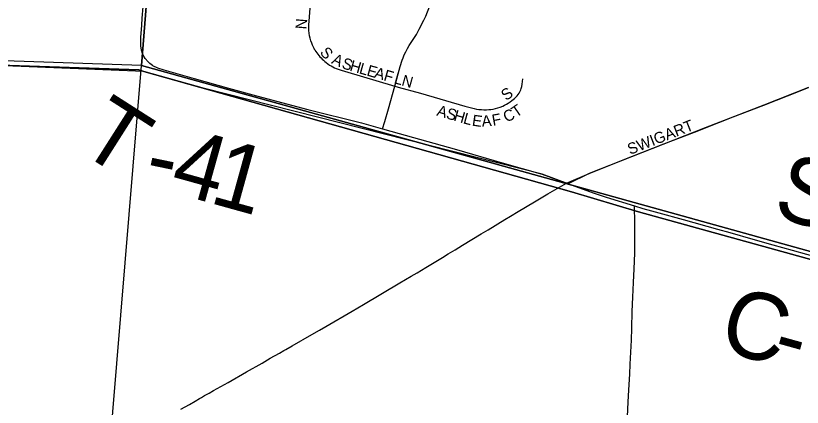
# Model space of a CAD drawing. Extents: x 1410790 to 1770854, y 448063 to 770588.
# Drawn here: x 1521556 to 1525089, y 615085 to 616842 of the extents above; entities that cross this region are included whole.
import ezdxf

# ---------------------------------------------------------------- set-up
doc = ezdxf.new("R2010")
doc.units = 0
for name, color, linetype in [('GM_X_City_Street', 7, 'Continuous'), ('GM_X_City_Street_Text', 7, 'Continuous'), ('GM_X_Corporation', 7, 'Continuous'), ('GM_X_County_Road', 7, 'Continuous'), ('GM_X_County_Road_Text', 7, 'Continuous'), ('GM_X_Section', 7, 'Continuous'), ('GM_X_Township', 7, 'Continuous'), ('GM_X_Township_Road', 7, 'Continuous'), ('GM_X_Township_Road_Text', 7, 'Continuous')]:
    doc.layers.add(name, color=color, linetype=linetype)

msp = doc.modelspace()

# ---------------------------------------------------------------- linework, layer by layer
at = {"layer": 'GM_X_City_Street'}
for points in [[(1522170.2, 616619.6), (1522158.5, 616627.2), (1522151.1, 616635), (1522137.6, 616650.4), (1522126.9, 616668.1), (1522120, 616687.5), (1522117.2, 616707.8), (1522117.6, 616744.5), (1522122.3, 616799.9), (1522123.6, 616831.2), (1522128.6, 616881.4), (1522135.7, 616983.1)], [(1523258.4, 616526.2), (1523283, 616614.2), (1523291.5, 616642.1), (1523295.9, 616654), (1523301.1, 616666.5), (1523307.8, 616680.5), (1523315.3, 616695), (1523323.1, 616709.2), (1523337.4, 616730.9), (1523355.4, 616758.6), (1523368.6, 616781.6), (1523389.4, 616822.8), (1523397.6, 616840.5), (1523405.7, 616859), (1523411.5, 616874.3), (1523417.1, 616890.1), (1523420.9, 616902.5), (1523424.2, 616915.8), (1523426.1, 616925.1), (1523427.7, 616935.7), (1523428.7, 616945.9), (1523428.9, 616955.5)], [(1522899.9, 616687.9), (1522896.1, 616694.8), (1522892.6, 616701.8), (1522888.7, 616710.2), (1522885.3, 616718.7), (1522882, 616729.1), (1522878.6, 616741.3), (1522875.9, 616752.6), (1522874.1, 616764.4), (1522872.9, 616775.6), (1522872.2, 616787.7), (1522872.6, 616802), (1522873.4, 616817.6), (1522878.2, 616876.8), (1522884.6, 616945.2)], [(1522899.9, 616687.9), (1522903.6, 616681.6), (1522907.7, 616675.5), (1522912.3, 616669.5), (1522917, 616663.8), (1522922.2, 616657.8), (1522927.2, 616652.7), (1522932.3, 616647.7), (1522938.3, 616642.1), (1522944.6, 616636.5), (1522950.7, 616631.7), (1522958.1, 616626.3), (1522965.7, 616621.1), (1522972.6, 616616.7), (1522980.2, 616612.6), (1522987.8, 616608.9), (1522995.5, 616605.8), (1523003.6, 616602.6), (1523017.3, 616598.1), (1523033, 616593.1), (1523258.4, 616526.2)], [(1523258.4, 616526.2), (1523273.4, 616522.1), (1523374.5, 616494), (1523573.5, 616436.8), (1523614.4, 616425.9), (1523626.1, 616423.6), (1523636.6, 616422), (1523647.6, 616421), (1523658.5, 616420.4), (1523670.2, 616420.4), (1523681.5, 616421), (1523689.9, 616421.8), (1523700.5, 616423.5), (1523711.2, 616425.7), (1523721.4, 616428.4), (1523732.5, 616432), (1523743.5, 616436.5), (1523751.8, 616440.3), (1523760.6, 616444.8), (1523768, 616449.4), (1523776.6, 616455.4), (1523784.1, 616461.1), (1523790.2, 616465.7), (1523796.9, 616471.3), (1523802.1, 616476.1), (1523808.1, 616482.4), (1523812.5, 616488.2), (1523817.1, 616495), (1523820.8, 616501.2), (1523824.1, 616509), (1523826.4, 616516), (1523828.6, 616524.7), (1523830.3, 616535.3), (1523833.4, 616558.4)], [(1523203.1, 616334.8), (1523213.1, 616368.1), (1523230, 616424.6), (1523258.4, 616526.2)], [(1524030, 616091.4), (1524131.4, 616134), (1524277.5, 616192.8), (1524467, 616267), (1524604.6, 616320), (1524714.4, 616363.5), (1524778.6, 616388.2), (1524916.1, 616440.7), (1525022.8, 616482.6), (1525116.2, 616520.4)]]:
    msp.add_lwpolyline(points, dxfattribs=at)
at = {"layer": 'GM_X_Corporation'}
msp.add_lwpolyline([(1525116.2, 616520.4), (1524916.1, 616440.7), (1524652.5, 616339), (1524131.4, 616134), (1524037.4, 616088.6), (1523920.1, 616131.6), (1522403.3, 616516.1), (1522130.9, 616592.7), (1521210.6, 616629.9)], dxfattribs=at)
at = {"layer": 'GM_X_County_Road'}
for points in [[(1522296.8, 615076.6), (1522335.9, 615098), (1522361.5, 615112.7), (1522381.1, 615124.4), (1522390.2, 615129.3), (1522403.8, 615137.5), (1522424.6, 615149.3), (1522443.8, 615160.7), (1522509.3, 615197.1), (1522591.6, 615243.6), (1522662.7, 615283.5), (1522699.1, 615305.4), (1522740.6, 615328.6), (1522760.6, 615339.9), (1522769.1, 615344.7), (1522797, 615361.7), (1522885.3, 615412.1), (1522919.5, 615431.6), (1522948.2, 615447.5), (1523067.7, 615516.1), (1523118, 615546.9), (1523281.8, 615643.7), (1523332.7, 615673.6), (1523358.4, 615688.1), (1523378.1, 615699.9), (1523397.7, 615711.8), (1523428.4, 615730.7), (1523473.2, 615757.9), (1523498, 615773.7), (1523529.1, 615792), (1523562.8, 615812.4), (1523604.8, 615837.9), (1523646.9, 615863.3), (1523677.8, 615881.9), (1523753.4, 615928.1), (1523778.5, 615943.4), (1523813.3, 615963.7), (1523885.5, 616006.8), (1523946.6, 616043.7), (1524030, 616091.4)], [(1524030, 616091.4), (1524088.4, 616069.3), (1524150.1, 616047), (1524207.7, 616028.5), (1524335.3, 615989.4)], [(1524335.3, 615989.4), (1524373.4, 615977.9), (1524411.2, 615967.2)], [(1524411.2, 615967.2), (1524445.2, 615957.5), (1524553.7, 615927.9), (1524707.6, 615885), (1524764.1, 615870), (1524866.1, 615840.2), (1524957.4, 615814.3), (1525044.2, 615790.1), (1525172.7, 615754.6)]]:
    msp.add_lwpolyline(points, dxfattribs=at)
at = {"layer": 'GM_X_Section'}
for points in [[(1522551.9, 622046.6), (1522119.9, 616619.5), (1516186.2, 616821.5), (1516639.8, 622176)], [(1527751.7, 620502.8), (1527349.3, 615167.2), (1522119.9, 616619.5), (1522551.9, 622046.6)], [(1522119.9, 616619.5), (1527349.3, 615167.2), (1526943.5, 609749.7), (1521677.3, 611270.6)]]:
    msp.add_lwpolyline(points, close=True, dxfattribs=at)
at = {"layer": 'GM_X_Township'}
for points in [[(1536959.1, 614403.3), (1531259.4, 614833.9), (1529991.4, 614929.8), (1529552.3, 614962.9), (1527330.8, 615130.8), (1527316.2, 615134.9), (1526855.2, 615264.5), (1525559.8, 615628.7), (1524353.6, 615961.7), (1524051.6, 616052.7), (1522130.9, 616592.7), (1522108.4, 616599.1), (1518670.6, 616715.2), (1518385.8, 616724.8), (1518142.2, 616733), (1517607.5, 616751.1), (1517456.2, 616756.2), (1517166.1, 616772.8), (1516773.1, 616795.4), (1516487.5, 616797.3), (1516179.6, 616799.3), (1516259.6, 617762.4), (1516373.4, 619132.2), (1516461.1, 620230.1)], [(1515651.7, 611077.8), (1515731.8, 611411.8), (1515919.3, 613667.1), (1515954.1, 614086), (1516097.7, 615813.6), (1516178.5, 616785.8), (1516179.6, 616799.3), (1516487.5, 616797.3), (1516773.1, 616795.4), (1517166.1, 616772.8), (1517456.2, 616756.2), (1517607.5, 616751.1), (1518142.2, 616733), (1518385.8, 616724.8), (1518670.6, 616715.2), (1522108.4, 616599.1), (1522130.9, 616592.7), (1524051.6, 616052.7), (1524353.6, 615961.7), (1525559.8, 615628.7)]]:
    msp.add_lwpolyline(points, dxfattribs=at)
at = {"layer": 'GM_X_Township_Road'}
for points in [[(1522170.2, 616619.6), (1522193.2, 616609.1), (1522221.3, 616599), (1522356.9, 616560.6), (1522511.3, 616516.7), (1522637.8, 616482.8), (1522868.2, 616422.1), (1523108.5, 616361.9), (1523203.1, 616334.8)], [(1523203.1, 616334.8), (1523240.9, 616323.9), (1523535.2, 616242), (1523740.2, 616182.7), (1523920.1, 616131.6), (1524030, 616091.4)], [(1524301.8, 615011.6), (1524307.4, 615108.3), (1524310.3, 615163.4), (1524313.6, 615233.9), (1524315.9, 615278.9), (1524321.1, 615386.8), (1524323.1, 615440.2), (1524324.7, 615514.4), (1524328.3, 615579.6), (1524331, 615645.2), (1524334.3, 615706.9), (1524337.2, 615776.1), (1524337.2, 615827.2), (1524336.9, 615886.3), (1524336.2, 615929.9), (1524335.6, 615970.9), (1524335.3, 615989.4)]]:
    msp.add_lwpolyline(points, dxfattribs=at)

# ---------------------------------------------------------------- texts
at = {"layer": 'GM_X_City_Street_Text'}
for s, rotation, p in [('N', 85.3943, (1522861.6, 616779.7)), ('S', 312.0522, (1522919.1, 616675.1)), ('A', 334.536, (1522971.3, 616629.9)), ('S', 340.9043, (1523016.6, 616608.7)), ('H', 343.967, (1523052.7, 616596.3)), ('L', 344.276, (1523095.2, 616584.1)), ('E', 344.2836, (1523129.1, 616574.5)), ('A', 344.2618, (1523163, 616565)), ('F', 344.2841, (1523205.4, 616553)), ('L', 344.2836, (1523252, 616539.9)), ('N', 344.2618, (1523285.8, 616530.4)), ('S', 36.8508, (1523759.1, 616458.6)), ('A', 343.6043, (1523443.5, 616394.9)), ('S', 343.6345, (1523485.7, 616382.5)), ('C', 23.7085, (1523758.8, 616362.7)), ('T', 34.6168, (1523804.1, 616383.7)), ('H', 343.7745, (1523519.6, 616372.5)), ('L', 344.854, (1523562.8, 616359.9)), ('E', 351.5193, (1523603, 616349.4)), ('A', 4.8141, (1523650.5, 616343.9)), ('F', 10.3289, (1523699.5, 616348.2)), ('SWIGART', 21.2963, (1524315.3, 616217.6))]:
    msp.add_text(s, height=50, rotation=rotation, dxfattribs=at).set_placement(p)
at = {"layer": 'GM_X_County_Road_Text'}
for s, rotation, p in [('STUTSMAN', 344.333, (1524949.2, 615944.1)), ('C', 344.4717, (1524703.8, 615345.5)), ('-', 344.481, (1524941.2, 615279.5))]:
    msp.add_text(s, height=300, rotation=rotation, dxfattribs=at).set_placement(p)
at = {"layer": 'GM_X_Township_Road_Text'}
for s, rotation, p in [('T', 327.4772, (1521825.6, 616243.3)), ('4', 344.4313, (1522240, 616054.5)), ('1', 344.507, (1522418.4, 616004.8)), ('-', 348.3404, (1522124.6, 616078.1))]:
    msp.add_text(s, height=300, rotation=rotation, dxfattribs=at).set_placement(p)

doc.saveas('drawing.dxf')
